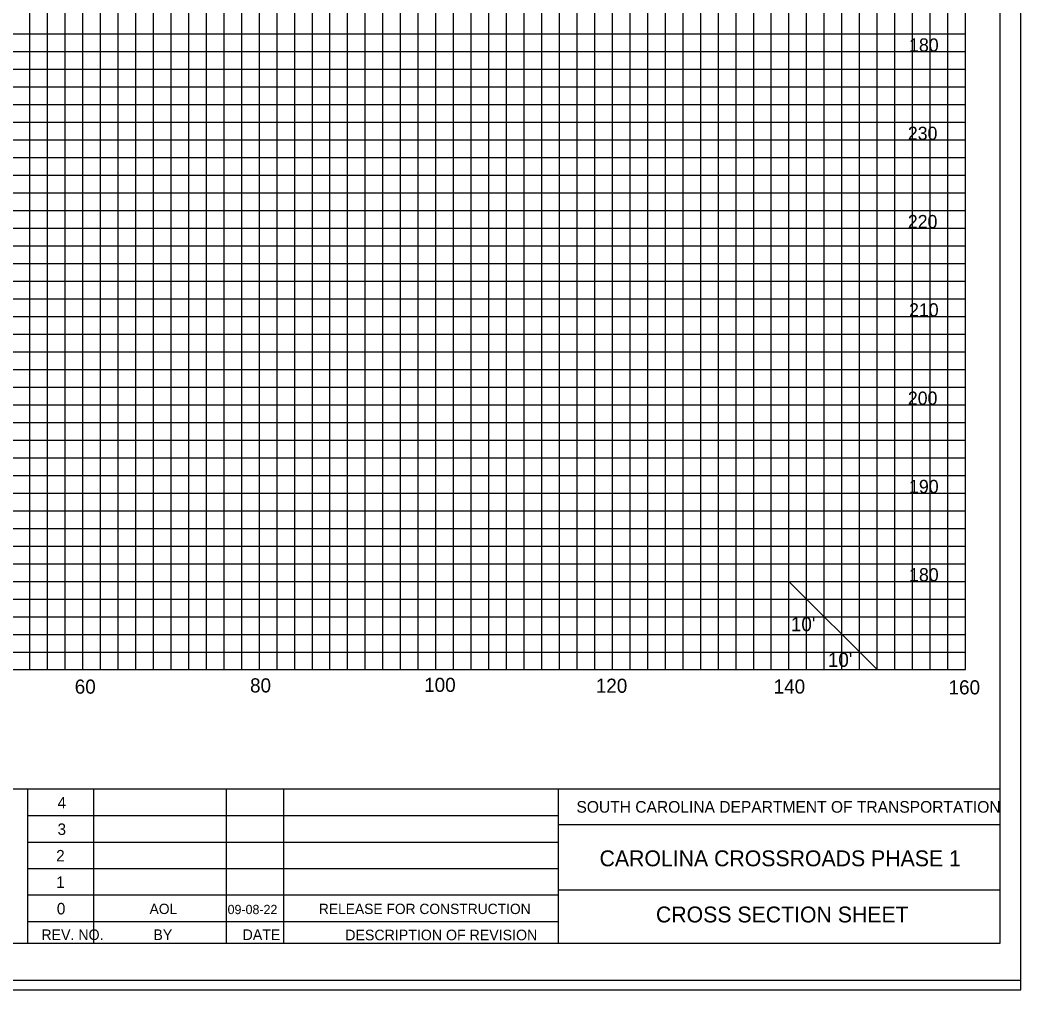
# Model space of a CAD drawing. Extents: x 967 to 1326, y 964 to 2584.
# Drawn here: x 1212.9 to 1326.3, y 1243.7 to 1353.6 of the extents above; entities that cross this region are included whole.
import ezdxf

# ---------------------------------------------------------------- set-up
doc = ezdxf.new("R2010")
doc.units = 0
for name, color, linetype in [('Default', 7, 'Continuous'), ('RD_SHT_Bndy', 7, 'Continuous'), ('RD_SHT_IplotShp', 7, 'Continuous'), ('RD_SHT_Misc1', 7, 'Continuous'), ('RD_SHT_MjGrid', 7, 'Continuous'), ('RD_SHT_MnGrid', 7, 'Continuous'), ('RD_SHT_TX', 7, 'Continuous'), ('RD_Sketch1', 7, 'Continuous')]:
    doc.layers.add(name, color=color, linetype=linetype)

msp = doc.modelspace()

# ---------------------------------------------------------------- linework, layer by layer
at = {"layer": 'RD_SHT_Bndy'}
for p, q in [((1323.89, 1458.46), (1323.89, 1248.98)), ((996.11, 1266.49), (1323.89, 1266.49)), ((1213.76, 1248.94), (1213.76, 1266.49)), ((1221.26, 1248.95), (1221.26, 1266.48)), ((1236.26, 1248.95), (1236.26, 1266.48)), ((1242.76, 1248.95), (1242.76, 1266.48)), ((1273.88, 1248.98), (1273.88, 1266.49)), ((1213.76, 1263.48), (1273.88, 1263.48)), ((1323.93, 1262.43), (1273.88, 1262.43)), ((1213.76, 1260.48), (1273.88, 1260.48)), ((1213.76, 1257.48), (1273.88, 1257.48)), ((1213.76, 1254.48), (1273.88, 1254.48)), ((1323.89, 1255.04), (1273.88, 1255.04)), ((1213.76, 1251.48), (1273.88, 1251.48)), ((1323.89, 1248.98), (996.11, 1248.98))]:
    msp.add_line(p, q, dxfattribs=at)
at = {"layer": 'RD_SHT_IplotShp'}
for points in [[(967.41, 1243.72), (1326.28, 1243.72), (1326.28, 1463.72), (967.41, 1463.72)], [(988.52, 1244.84), (1326.28, 1244.84), (1326.28, 1462.6), (988.52, 1462.6)]]:
    msp.add_lwpolyline(points, close=True, dxfattribs=at)
at = {"layer": 'RD_SHT_MjGrid'}
for p, q in [((1220, 1280), (1220, 1450)), ((1230, 1280), (1230, 1450)), ((1240, 1280), (1240, 1450)), ((1250, 1280), (1250, 1450)), ((1260, 1280), (1260, 1450)), ((1270, 1280), (1270, 1450)), ((1280, 1280), (1280, 1450)), ((1290, 1280), (1290, 1450)), ((1300, 1280), (1300, 1450)), ((1310, 1280), (1310, 1450)), ((1320, 1280), (1320, 1450)), ((1000, 1350), (1320, 1350)), ((1000, 1340), (1320, 1340)), ((1000, 1330), (1320, 1330)), ((1000, 1320), (1320, 1320)), ((1000, 1310), (1320, 1310)), ((1000, 1300), (1320, 1300)), ((1000, 1290), (1320, 1290)), ((1000, 1280), (1320, 1280))]:
    msp.add_line(p, q, dxfattribs=at)
at = {"layer": 'RD_SHT_MnGrid'}
for p, q in [((1214, 1280), (1214, 1450)), ((1216, 1280), (1216, 1450)), ((1218, 1280), (1218, 1450)), ((1222, 1280), (1222, 1450)), ((1224, 1280), (1224, 1450)), ((1226, 1280), (1226, 1450)), ((1228, 1280), (1228, 1450)), ((1232, 1280), (1232, 1450)), ((1234, 1280), (1234, 1450)), ((1236, 1280), (1236, 1450)), ((1238, 1280), (1238, 1450)), ((1242, 1280), (1242, 1450)), ((1244, 1280), (1244, 1450)), ((1246, 1280), (1246, 1450)), ((1248, 1280), (1248, 1450)), ((1252, 1280), (1252, 1450)), ((1254, 1280), (1254, 1450)), ((1256, 1280), (1256, 1450)), ((1258, 1280), (1258, 1450)), ((1262, 1280), (1262, 1450)), ((1264, 1280), (1264, 1450)), ((1266, 1280), (1266, 1450)), ((1268, 1280), (1268, 1450)), ((1272, 1280), (1272, 1450)), ((1274, 1280), (1274, 1450)), ((1276, 1280), (1276, 1450)), ((1278, 1280), (1278, 1450)), ((1282, 1280), (1282, 1450)), ((1284, 1280), (1284, 1450)), ((1286, 1280), (1286, 1450)), ((1288, 1280), (1288, 1450)), ((1292, 1280), (1292, 1450)), ((1294, 1280), (1294, 1450)), ((1296, 1280), (1296, 1450)), ((1298, 1280), (1298, 1450)), ((1302, 1280), (1302, 1450)), ((1304, 1280), (1304, 1450)), ((1306, 1280), (1306, 1450)), ((1308, 1280), (1308, 1450)), ((1312, 1280), (1312, 1450)), ((1314, 1280), (1314, 1450)), ((1316, 1280), (1316, 1450)), ((1318, 1280), (1318, 1450)), ((1000, 1352), (1320, 1352)), ((1000, 1348), (1320, 1348)), ((1000, 1346), (1320, 1346)), ((1000, 1344), (1320, 1344)), ((1000, 1342), (1320, 1342)), ((1000, 1338), (1320, 1338)), ((1000, 1336), (1320, 1336)), ((1000, 1334), (1320, 1334)), ((1000, 1332), (1320, 1332)), ((1000, 1328), (1320, 1328)), ((1000, 1326), (1320, 1326)), ((1000, 1324), (1320, 1324)), ((1000, 1322), (1320, 1322)), ((1000, 1318), (1320, 1318)), ((1000, 1316), (1320, 1316)), ((1000, 1314), (1320, 1314)), ((1000, 1312), (1320, 1312)), ((1000, 1308), (1320, 1308)), ((1000, 1306), (1320, 1306)), ((1000, 1304), (1320, 1304)), ((1000, 1302), (1320, 1302)), ((1000, 1298), (1320, 1298)), ((1000, 1296), (1320, 1296)), ((1000, 1294), (1320, 1294)), ((1000, 1292), (1320, 1292)), ((1000, 1288), (1320, 1288)), ((1000, 1286), (1320, 1286)), ((1000, 1284), (1320, 1284)), ((1000, 1282), (1320, 1282))]:
    msp.add_line(p, q, dxfattribs=at)
at = {"layer": 'RD_SHT_TX'}
msp.add_line((1300, 1290), (1310, 1280), dxfattribs=at)
at = {"layer": 'RD_Sketch1'}
msp.add_lwpolyline([(967.41, 1243.72), (1326.28, 1243.72), (1326.28, 1463.72), (967.41, 1463.72)], close=True, dxfattribs=at)

# ---------------------------------------------------------------- texts
at = {"layer": 'Default'}
for s, p in [('180', (1313.61, 1350)), ('230', (1313.47, 1340)), ('220', (1313.47, 1330)), ('210', (1313.61, 1320)), ('200', (1313.47, 1310)), ('190', (1313.61, 1300)), ('180', (1313.61, 1290))]:
    msp.add_text(s, height=1.5, dxfattribs=at).set_placement(p)
at = {"layer": 'RD_SHT_Misc1'}
for s, height, p in [('AOL', 1.17, (1227.56, 1252.32)), ('09-08-22', 1.053, (1236.4, 1252.31)), ('RELEASE FOR CONSTRUCTION', 1.17, (1246.74, 1252.32))]:
    msp.add_text(s, height=height, dxfattribs=at).set_placement(p)
at = {"layer": 'RD_SHT_TX'}
for s, height, p in [("10'", 1.6, (1300.21, 1284.36)), ("10'", 1.6, (1304.4, 1280.32)), ('60', 1.6, (1219.08, 1277.28)), ('80', 1.6, (1238.94, 1277.42)), ('100', 1.6, (1258.67, 1277.48)), ('120', 1.6, (1278.11, 1277.38)), ('140', 1.6, (1298.26, 1277.29)), ('160', 1.6, (1318.08, 1277.2)), ('4', 1.3, (1217.13, 1264.28)), ('SOUTH CAROLINA DEPARTMENT OF TRANSPORTATION', 1.32, (1275.92, 1263.8)), ('3', 1.3, (1217.13, 1261.28)), ('2', 1.3, (1216.97, 1258.28)), ('1', 1.3, (1216.97, 1255.28)), ('0', 1.3, (1217.05, 1252.28)), ('REV. NO.', 1.2, (1215.3, 1249.38)), ('BY', 1.2, (1227.99, 1249.38)), ('DATE', 1.2, (1238.1, 1249.38)), ('DESCRIPTION OF REVISION', 1.2, (1249.73, 1249.35))]:
    msp.add_text(s, height=height, dxfattribs=at).set_placement(p)
for s, p in [('CAROLINA CROSSROADS PHASE 1', (1278.54, 1257.73)), ('CROSS SECTION SHEET', (1284.93, 1251.37))]:
    msp.add_text(s, height=1.8, rotation=0, dxfattribs=at).set_placement(p)

doc.saveas('drawing.dxf')
